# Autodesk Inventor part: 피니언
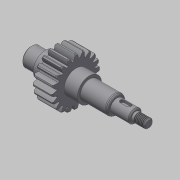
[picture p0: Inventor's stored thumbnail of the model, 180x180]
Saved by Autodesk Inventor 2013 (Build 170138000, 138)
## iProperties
Created: 2019-06
Part Number: 피니언
Material: 스테인리스강
Document SubType Name: Modeling
Designer: mduedu
Density: 1 g/cm^3
Author: mduedu
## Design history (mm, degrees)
sketch "스케치1"
  geometry: L1 (0, 0)-(13, 0); L2 (13, 0)-(13, 8.5); L3 (13, 8.5)-(0, 8.5); L4 (0, 8.5)-(0, 0); L5 (13, 0)-(53, 0); L6 (53, 0)-(53, 11); L7 (53, 11)-(13, 11); L8 (13, 11)-(13, 0); L9 (53, 0)-(78, 0); L10 (78, 0)-(78, 8.5); L11 (78, 8.5)-(53, 8.5); L12 (53, 8.5)-(53, 0); L13 (78, 0)-(95, 0); L14 (95, 0)-(95, 6); L15 (95, 6)-(78, 6); L16 (78, 6)-(78, 0); L17 (95, 0)-(107, 0); L18 (107, 0)-(107, 4); L19 (107, 4)-(95, 4); L20 (95, 4)-(95, 0)
  constraints: 40 end point, 10 parallel, 5 horizontal, 5 perpendicular
  dimensions: "d0" = 107 distance between parallel lines of L18 L4; "d2" = 78 distance between parallel lines of L10 L4; "d3" = 40 distance of L6.end L7.end; "d4" = 25 distance of L10.end L11.end; "d5" = 17 distance of L14.end L15.end; "d6" = 8 diameter of L19 L17; "d7" = 12 diameter of L15 L13; "d8" = 17 diameter of L11 L9; "d9" = 22 diameter of L7 L5; "d10" = 17 diameter of L3 L1
revolve "회전1" sketch "스케치1" stored, may be unused: angle "d11" = 90 deg
node "작업 평면1"
sketch "스케치2"
  geometry: C1 r 17.5 at (0, 0); C2 r 20 at (0, 0); C3 r 22 at (0, 0); 1 further point
  constraints: 3 centre point, 3 coincident
  dimensions: "d13" = 40 diameter of C2; "d15" = 44 diameter of C3; "d16" = 35 diameter of C1
extrude "돌출1" join sketch "스케치2" distance "d17" = 18; taper "d18" = 0 deg
sketch "스케치3"
  geometry: L1 (0, 0)-(22, 0); L2 (0, 0)-(0, 22); L3 (0.57, 0)-(0.57, 22); L4 (1.57, 0)-(1.57, 22); L5 (2.07, 0)-(2.07, 22); A1 r 22 centre (0, 0) between (22, 0) and (0, 22) reference; A2 r 9.495 centre (-7.411, 16.856) between (2.07, 17.377) and (0.57, 22); A3 r 9.495 centre (7.411, 16.856) between (-0.57, 22) and (-2.07, 17.377); A4 r 17.5 centre (0, 0) between (2.07, 17.377) and (-2.07, 17.377); A5 r 22.007 centre (0, 0) between (0.57, 22) and (-0.57, 22); 4 further points
  constraints: 11 point on circle, 10 end point, 6 parallel, 5 point on line, 4 centre point, 3 symmetric about line, 2 coincident, 1 horizontal, 1 perpendicular, 5 other
  dimensions: "d19" = 0.5 distance between parallel lines of L5 L4; "d21" = 1 distance between parallel lines of L3 L4; "d22" = 1.57 distance between parallel lines of L2 L4
extrude "돌출2" join sketch "스케치3" stored distance "d23" = 18; taper "d24" = 0 deg
chamfer "모따기1" distance "d25" = 1; stored, may be unused: second distance "d26" = 2, angle "d27" = 45 deg
fillet "모깎기1" dims "d31" = 0.3
chamfer "모따기2" distance "d32" = 1; stored, may be unused: second distance "d33" = 2, angle "d34" = 45 deg
node "작업 평면2"
sketch "스케치4"
  geometry: L1 (3.5, -2)-(-2.5, -2); L2 (-2.5, 2)-(3.5, 2); L3 (8.5, 8.5)-(8.5, -8.5) reference; A1 r 2 centre (3.5, 0) between (3.5, -2) and (3.5, 2); A2 r 2 centre (-2.5, 0) between (-2.5, 2) and (-2.5, -2); 1 further point
  constraints: 4 end point, 4 point on circle, 4 tangent, 2 centre point, 1 horizontal, 1 horizontal alignment, 1 parallel
  dimensions: "d35" = 3 distance edge to line of A1 L3; "d36" = 10 dimension on A2 A1; "d37" = 4 distance between parallel lines of L2 L1
extrude "돌출3" cut sketch "스케치4" distance "d38" = 2.5; taper "d39" = 0 deg
chamfer "모따기3" distance "d40" = 1.82; stored, may be unused: second distance "d41" = 2, angle "d42" = 30 deg
fillet "모깎기2" dims "d43" = 1, "d44" = 2
chamfer "모따기4" distance "d45" = 1; stored, may be unused: second distance "d46" = 2, angle "d47" = 30 deg
feature "스레드1" dims "d48" = 10, "d49" = 0
chamfer "모따기5" distance "d50" = 1; stored, may be unused: second distance "d51" = 2, angle "d52" = 30 deg
node "솔리드1"
pattern_circular "원형 패턴1" dims angle "d29" = 360 deg
other parameters: "d12" = -12
